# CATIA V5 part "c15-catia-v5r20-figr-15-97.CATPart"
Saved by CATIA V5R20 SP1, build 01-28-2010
Part number: Part1
Bounding box of the stored display mesh (mm): x -66.07 to 66.07, y -35.456 to 35.456, z -8 to 1
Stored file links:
  D:\v5_r20\psrt_files_downloaded\c15\c15-catia-v5r20-figr-15-97.CATPart
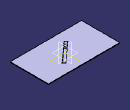
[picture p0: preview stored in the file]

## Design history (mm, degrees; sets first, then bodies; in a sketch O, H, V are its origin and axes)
SheetMetalParameters1: Thickness 1, BendRadius 5, KFactor 0.5 {= log(min(100,max(20*SheetMetalParameters1.BendRadius,SheetMetalParameters1.Thickness)/SheetMetalParameters1.Thickness))/log(100)/2}, ReliefRadialLength 1, ReliefAxialLength 2, MinimumBendRadius 0
Body1 (main body)
  Sketch1 on xy-plane, origin (0, 0, 0), H (1, 0, 0), V (0, 1, 0)
    line L1 (66.07, 35.4565) -> (66.07, -35.4565)
    line L2 (66.07, -35.4565) -> (-66.07, -35.4565)
    line L3 (-66.07, -35.4565) -> (-66.07, 35.4565)
    line L4 (-66.07, 35.4565) -> (66.07, 35.4565)
    vertical: L1 V, L3 V
    horizontal: L2 H, L4 H
    equidistance: L1 L3 O, L2 L4 O
  Wall1: Thickness 1, Profile Sketch1
  Sketch2 on face of Wall1, origin (0, 0, 1), H (1, 0, 0), V (0, 1, 0)
    point P1 (0, 0)
    coincidence: P1 O
  Sketch3 on face of Wall1, origin (0, 0, 1), H (1, 0, 0), V (0, 1, 0)
    point P1 (0, 0)
    reference projected point E1 (0, 0) from Sketch2.P1
    coincidence: E1 P1
  d_Stamp1: Stamp_FilletRadius 2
